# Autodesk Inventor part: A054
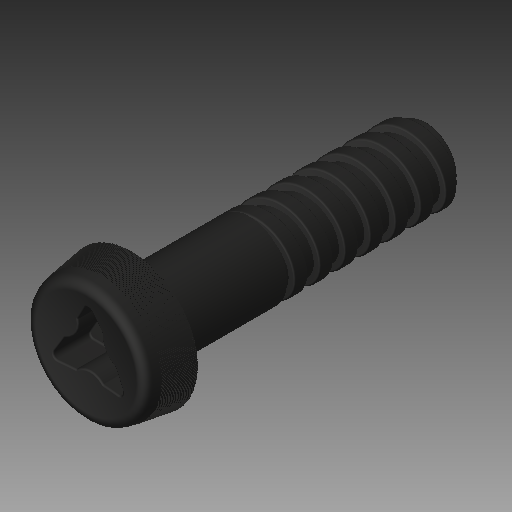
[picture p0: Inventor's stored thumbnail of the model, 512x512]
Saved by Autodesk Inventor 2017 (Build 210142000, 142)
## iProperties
Created: 2012-03
Part Number: A054
Material: Générique
Document SubType Name: Modeling
Designer: ficho
Density: 1 g/cm^3
Appearance: Par défaut
Mass: 2.80068 g
Surface Area: 19.9154 cm^2
Volume: 2.80068 cm^3
Sending System: Autodesk Inventor 2012
Preprocessor: Autodesk Inventor 2012
Title: C:\# CARLOS\MECANO\mecano-Componentes\A054.stp
Author: cv
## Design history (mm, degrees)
feature "Solid1"
node "Solide1"
